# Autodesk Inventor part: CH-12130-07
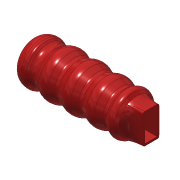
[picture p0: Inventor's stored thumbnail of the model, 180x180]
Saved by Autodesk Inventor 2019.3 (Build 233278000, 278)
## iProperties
Created: 2012-09
Part Number: CH-12130-07
Material: Ogólny
Document SubType Name: Modeling
Designer: CADENGINEERING4
Density: 1 g/cm^3
Appearance: Jasnoczerwona
Author: CADENGINEERING4
Revision Number: ÈÎºÎ
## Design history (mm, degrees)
feature "Ô²½Ç11"
node "Bryła1"
